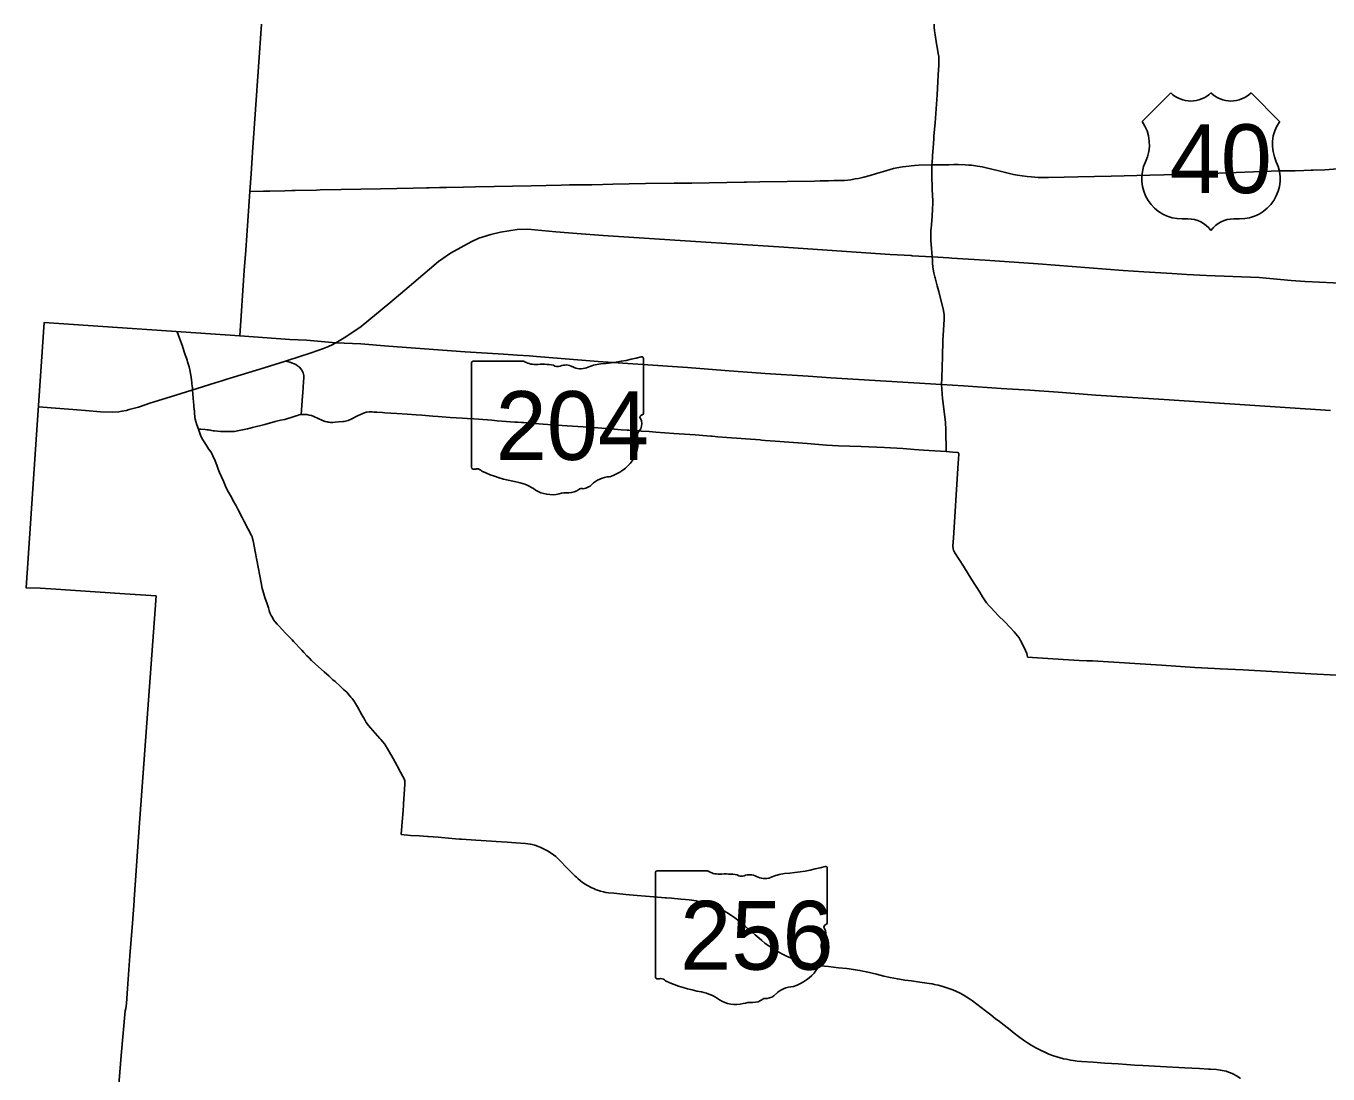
# Model space of a CAD drawing. Extents: x 1761803 to 2441803, y 509895 to 949895.
# Drawn here: x 1880621 to 1933337, y 771732 to 814167 of the extents above; entities that cross this region are included whole.
import ezdxf

# ---------------------------------------------------------------- set-up
doc = ezdxf.new("R2010")
doc.units = 0
for name, color, linetype in [('GM_X_County', 7, 'Continuous'), ('GM_X_County_Road_Text', 7, 'Continuous'), ('GM_X_Minor_Lake', 7, 'Continuous'), ('GM_X_Minor_River', 7, 'Continuous'), ('GM_X_Minor_River_Text', 7, 'Continuous'), ('GM_X_Township_Road', 7, 'Continuous')]:
    doc.layers.add(name, color=color, linetype=linetype)

msp = doc.modelspace()

# ---------------------------------------------------------------- linework, layer by layer
at = {"layer": 'GM_X_County'}
for points in [[(1890151, 814240), (1889790, 809054), (1889730, 808187), (1889680, 807466), (1889514, 805092), (1889457, 804269), (1889273, 801617), (1891303, 801473), (1891975, 801450), (1893167, 801341), (1894181, 801293), (1895291, 801208), (1898404, 800970), (1899948, 800886), (1900525, 800845), (1900989, 800810), (1901286, 800791), (1903789, 800582), (1907402, 800335), (1908911, 800219), (1910549, 800095), (1912289, 799987), (1913214, 799928), (1917684, 799645), (1918576, 799593), (1920103, 799495), (1921268, 799418), (1922415, 799341), (1923944, 799214), (1926704, 799049), (1933445, 798603)], [(1889273, 801617), (1881354, 802158), (1880996, 796827), (1880621, 791420), (1881199, 791408), (1881620, 791382), (1884619, 791174), (1885889, 791091), (1885509, 785950), (1885182, 781522), (1884997, 778795), (1885000, 778743), (1884928, 777838), (1884830, 776510), (1884735, 775195), (1884687, 774579), (1884665, 774383), (1884630, 774290), (1884479, 772480), (1884260, 769783)]]:
    msp.add_lwpolyline(points, dxfattribs=at)
at = {"layer": 'GM_X_County_Road_Text'}
for p, q in [((1926973, 811463), (1925812, 810303)), ((1931381, 810303), (1930221, 811463)), ((1927437, 806358), (1927669, 806358)), ((1929525, 806358), (1929757, 806358))]:
    msp.add_line(p, q, dxfattribs=at)
for centre, radius, start, end in [((1927785, 812291), 1160, 225.573, 314.427), ((1929409, 812291), 1160, 225.573, 314.427), ((1924482, 809371), 1624, 334.5471, 35.0009), ((1932712, 809371), 1624, 144.9991, 205.4529), ((1927418, 807982), 1624, 154.8319, 270.6383), ((1929775, 807982), 1624, 269.3617, 25.1681), ((1927669, 805198), 1160, 36.8699, 90), ((1929525, 805198), 1160, 90, 143.1301)]:
    msp.add_arc(centre, radius, start, end, dxfattribs=at)
at = {"layer": 'GM_X_Minor_Lake'}
for points in [[(1917501, 813385), (1917491, 813445), (1917428, 813817), (1917410, 813975), (1917397, 814123), (1917398, 814247)], [(1917384, 809726), (1917428, 810245), (1917510, 811384), (1917540, 811910), (1917553, 812190), (1917575, 812580), (1917584, 812745), (1917577, 812929), (1917560, 813054), (1917526, 813229), (1917501, 813385)], [(1917360, 809403), (1917375, 809622), (1917384, 809726)], [(1917321, 808864), (1917325, 808927), (1917360, 809403)], [(1917308, 808648), (1917321, 808864)], [(1917296, 808208), (1917294, 808313), (1917302, 808540)], [(1917316, 807481), (1917311, 807589), (1917308, 807780), (1917302, 807946), (1917296, 808208)], [(1917302, 808540), (1917308, 808648)], [(1917306, 806453), (1917307, 806463), (1917325, 806747), (1917333, 806993), (1917333, 807020), (1917320, 807386), (1917316, 807481)], [(1917260, 805846), (1917261, 805903), (1917265, 805967), (1917279, 806129)], [(1917279, 806129), (1917280, 806143), (1917306, 806453)], [(1917310, 804823), (1917310, 804823), (1917264, 805339), (1917256, 805481), (1917257, 805733), (1917260, 805846)], [(1917415, 804018), (1917373, 804171), (1917342, 804404), (1917325, 804572), (1917318, 804685), (1917310, 804823)], [(1917568, 803452), (1917513, 803648), (1917428, 803971), (1917415, 804018)], [(1917684, 799645), (1917698, 799926), (1917725, 800792), (1917745, 801424), (1917797, 802299), (1917797, 802469), (1917775, 802653), (1917577, 803419), (1917568, 803452)], [(1886742, 801790), (1886797, 801638), (1886957, 801199), (1886960, 801190)], [(1886742, 801790), (1886797, 801638), (1886957, 801199), (1886960, 801190)], [(1886960, 801190), (1887070, 800859), (1887119, 800716), (1887142, 800633)], [(1887142, 800633), (1887162, 800563), (1887224, 800365), (1887258, 800242), (1887285, 800095), (1887307, 799953), (1887318, 799830)], [(1891121, 800590), (1891298, 800552), (1891414, 800515), (1891539, 800466), (1891615, 800409), (1891689, 800354), (1891753, 800283), (1891793, 800229), (1891846, 800118), (1891864, 800015), (1891864, 799918), (1891856, 799758)], [(1887318, 799830), (1887328, 799727), (1887336, 799666)], [(1891856, 799758), (1891832, 799322), (1891820, 799176)], [(1887336, 799666), (1887344, 799605), (1887355, 799491), (1887359, 799421), (1887404, 798931), (1887416, 798829), (1887420, 798773), (1887440, 798543), (1887447, 798459), (1887453, 798369), (1887461, 798315), (1887472, 798247), (1887473, 798243)], [(1891820, 799176), (1891762, 798437)], [(1917882, 796932), (1917868, 797816), (1917846, 798109), (1917804, 798456), (1917729, 799085), (1917684, 799645)], [(1887473, 798243), (1887493, 798159), (1887536, 798018), (1887599, 797836)], [(1889589, 797852), (1889794, 797906), (1890292, 798037), (1890712, 798152), (1890930, 798208), (1891098, 798238), (1891473, 798351), (1891564, 798381)], [(1891564, 798381), (1891616, 798398), (1891683, 798421), (1891762, 798437)], [(1891762, 798437), (1891888, 798437), (1891985, 798432), (1892088, 798415), (1892178, 798394), (1892280, 798352), (1892624, 798191), (1892729, 798155), (1892814, 798133), (1892859, 798125), (1892900, 798121), (1892944, 798118), (1892992, 798118), (1893037, 798119), (1893143, 798127), (1893274, 798135), (1893450, 798151), (1893507, 798159), (1893557, 798168), (1893666, 798199), (1893784, 798250), (1894044, 798381), (1894163, 798440), (1894226, 798470), (1894280, 798491), (1894329, 798509), (1894395, 798525), (1894420, 798530), (1894517, 798538), (1894632, 798540), (1894709, 798536), (1894825, 798528)], [(1894825, 798528), (1895061, 798512), (1895148, 798506), (1895639, 798473), (1896057, 798446), (1896422, 798418), (1896652, 798403), (1897098, 798371), (1897305, 798356), (1897796, 798320), (1898281, 798291), (1898484, 798273), (1898748, 798255), (1899303, 798214), (1899477, 798201), (1899692, 798185), (1900063, 798158), (1900414, 798130), (1900529, 798123), (1900689, 798112)], [(1887599, 797836), (1887683, 797605), (1887727, 797506), (1887777, 797415), (1887827, 797336), (1887925, 797182), (1888013, 797049), (1888098, 796930), (1888157, 796825), (1888191, 796764), (1888237, 796648)], [(1887599, 797836), (1887692, 797836), (1887868, 797826), (1887950, 797820), (1888008, 797812), (1888074, 797799), (1888091, 797796)], [(1888091, 797796), (1888144, 797784), (1888200, 797775), (1888249, 797769), (1888497, 797751), (1888789, 797742), (1888802, 797742)], [(1888802, 797742), (1888967, 797743), (1889068, 797754), (1889251, 797789), (1889386, 797811), (1889589, 797852)], [(1900689, 798112), (1900757, 798108), (1900954, 798094), (1901199, 798076), (1902115, 798011), (1903596, 797909)], [(1903596, 797909), (1904452, 797836), (1904713, 797820), (1904959, 797807), (1905034, 797803), (1905302, 797787), (1905547, 797767), (1905858, 797745), (1906127, 797727), (1906856, 797673), (1907714, 797613)], [(1907714, 797613), (1908193, 797574), (1908346, 797561)], [(1908346, 797561), (1908399, 797556), (1908634, 797537), (1908994, 797508), (1910347, 797406), (1910399, 797402)], [(1910399, 797402), (1910555, 797390)], [(1910555, 797390), (1910958, 797359), (1912250, 797260), (1913034, 797198), (1913513, 797172), (1914434, 797137), (1915385, 797102), (1916119, 797054), (1916582, 797017), (1916959, 796997), (1917882, 796932)], [(1888237, 796648), (1888247, 796623), (1888340, 796380), (1888402, 796223), (1888461, 796085), (1888614, 795732), (1888698, 795531), (1888779, 795363), (1888853, 795230), (1888934, 795090), (1889001, 794974), (1889128, 794738), (1889210, 794582), (1889373, 794259), (1889452, 794099), (1889615, 793791), (1889690, 793646), (1889726, 793579), (1889750, 793532), (1889772, 793481), (1889794, 793416), (1889814, 793324), (1889871, 793042), (1889898, 792895), (1889968, 792533), (1890143, 791624), (1890186, 791397), (1890208, 791310), (1890236, 791213), (1890293, 791028), (1890382, 790774), (1890436, 790609), (1890466, 790504), (1890498, 790409), (1890518, 790352), (1890546, 790294), (1890567, 790256), (1890594, 790210), (1890643, 790128), (1890702, 790045), (1890785, 789948), (1890807, 789927)], [(1917882, 796932), (1918148, 796915), (1918344, 796901), (1918376, 796884), (1918381, 796876), (1918383, 796867), (1918384, 796848), (1918384, 796828), (1918346, 796263), (1918170, 793425), (1918153, 793114), (1918155, 792998), (1918177, 792939), (1918232, 792838), (1918582, 792290), (1918920, 791748), (1919239, 791239), (1919347, 791058), (1919514, 790811), (1919623, 790682), (1919698, 790602), (1919834, 790464), (1920003, 790289), (1920236, 790055), (1920481, 789802), (1920632, 789635), (1920771, 789468), (1920828, 789393), (1920890, 789288), (1920942, 789188), (1921086, 788878), (1921140, 788759), (1921161, 788697), (1921174, 788612)], [(1890807, 789927), (1890837, 789896), (1891142, 789571), (1891173, 789539)], [(1891173, 789539), (1891395, 789308)], [(1891395, 789308), (1891456, 789244), (1891791, 788887), (1891870, 788803)], [(1891870, 788803), (1891996, 788670), (1892086, 788577), (1892184, 788481), (1892466, 788224)], [(1892466, 788224), (1892697, 788014), (1892891, 787837), (1893047, 787696)], [(1921174, 788612), (1921784, 788573), (1922832, 788507), (1923267, 788480), (1923569, 788461), (1923801, 788461), (1926597, 788281), (1927949, 788195), (1928747, 788145), (1928972, 788135), (1929900, 788094), (1931066, 788028), (1932642, 787931), (1933679, 787882), (1933866, 787871), (1934236, 787845), (1934539, 787836), (1938763, 787625), (1939615, 787583)], [(1893047, 787696), (1893132, 787619), (1893344, 787430), (1893478, 787306), (1893604, 787189), (1893709, 787076), (1893777, 786996), (1893826, 786931), (1893915, 786796), (1894036, 786599), (1894218, 786275), (1894323, 786097), (1894398, 785968), (1894485, 785842), (1894565, 785743), (1894664, 785638), (1894757, 785533), (1894944, 785323), (1894990, 785272), (1895072, 785182), (1895136, 785102), (1895174, 785047)], [(1895174, 785047), (1895182, 785035), (1895246, 784931), (1895482, 784509), (1895648, 784205), (1895788, 783947), (1895881, 783778), (1895929, 783684), (1895946, 783638), (1895957, 783600), (1895964, 783555), (1895963, 783472), (1895947, 783260), (1895904, 782667), (1895900, 782619)], [(1895900, 782619), (1895885, 782406), (1895861, 782094), (1895838, 781768), (1895811, 781424)], [(1895811, 781424), (1896186, 781394), (1896551, 781369), (1896877, 781344)], [(1896877, 781344), (1896908, 781342), (1897304, 781317), (1897442, 781306), (1898013, 781253), (1898167, 781244)], [(1898167, 781244), (1898253, 781239), (1898834, 781201)], [(1898834, 781201), (1899470, 781160), (1899655, 781147), (1900103, 781119), (1900447, 781098), (1900844, 781068), (1900935, 781057), (1901036, 781039), (1901119, 781021), (1901221, 780995), (1901337, 780956), (1901469, 780904), (1901629, 780828), (1901741, 780763), (1901887, 780674), (1901979, 780606), (1902070, 780532), (1902240, 780374), (1902524, 780085), (1902861, 779743), (1902903, 779703), (1902960, 779650), (1903070, 779555), (1903144, 779499), (1903230, 779436), (1903360, 779360), (1903504, 779281), (1903660, 779212), (1903672, 779207)], [(1903672, 779207), (1903765, 779170), (1903886, 779133), (1904001, 779104), (1904097, 779086), (1904206, 779071), (1904421, 779047), (1904901, 779005), (1905367, 778964), (1906039, 778908), (1906495, 778867), (1906548, 778864)], [(1906548, 778864), (1906756, 778848), (1907132, 778813), (1907327, 778796), (1907470, 778786), (1907569, 778771), (1907754, 778739), (1907894, 778709), (1908045, 778669), (1908234, 778613), (1908468, 778526), (1908627, 778461), (1908786, 778382), (1908881, 778332), (1909000, 778264), (1909185, 778150), (1909323, 778051), (1909434, 777967), (1909546, 777880), (1909650, 777793), (1909746, 777709), (1909839, 777625), (1910022, 777469), (1910146, 777364), (1910306, 777229), (1910409, 777137), (1910536, 777035), (1910706, 776913), (1910818, 776836), (1910918, 776772), (1911103, 776663), (1911251, 776583), (1911386, 776519), (1911513, 776459), (1911676, 776394), (1911869, 776323), (1912026, 776272), (1912146, 776238), (1912291, 776202), (1912446, 776169), (1912610, 776138), (1912792, 776117), (1913108, 776081), (1913522, 776034), (1913859, 775997), (1914120, 775965), (1914197, 775955), (1914378, 775924), (1914501, 775897), (1914651, 775861), (1915056, 775769), (1915360, 775698), (1915614, 775639), (1915762, 775607), (1915905, 775579), (1915992, 775567), (1916203, 775534), (1916470, 775497), (1916805, 775450), (1917005, 775425), (1917187, 775398), (1917311, 775379), (1917412, 775359), (1917555, 775329), (1917700, 775292), (1917871, 775240), (1918025, 775186), (1918149, 775135), (1918293, 775075), (1918412, 775014), (1918566, 774934), (1918713, 774844), (1918824, 774774), (1918943, 774691), (1919124, 774554), (1919291, 774425), (1919469, 774285), (1919680, 774125), (1919862, 773984), (1920037, 773850), (1920221, 773705), (1920471, 773517), (1920634, 773390), (1920806, 773253), (1921013, 773098), (1921172, 772989), (1921319, 772897), (1921506, 772788), (1921696, 772690), (1921897, 772598), (1922031, 772540), (1922187, 772485), (1922358, 772427), (1922633, 772351), (1922744, 772333), (1922918, 772295), (1923021, 772273), (1923184, 772255), (1923354, 772239), (1923829, 772206), (1924306, 772171), (1924844, 772137), (1925181, 772114), (1925506, 772092), (1925842, 772078), (1926553, 772036), (1927541, 771981), (1927829, 771970), (1928142, 771949), (1928503, 771927), (1928580, 771922)], [(1928580, 771922), (1928822, 771907), (1928978, 771889), (1929138, 771858), (1929210, 771840), (1929303, 771809), (1929386, 771777), (1929489, 771739), (1929638, 771652), (1929779, 771559), (1929802, 771542)]]:
    msp.add_lwpolyline(points, dxfattribs=at)
at = {"layer": 'GM_X_Minor_River'}
for points in [[(1893167, 801341), (1893576, 801576), (1894194, 802002), (1895349, 802960), (1896136, 803624), (1896321, 803779), (1897320, 804631), (1897808, 804965), (1898638, 805432), (1898953, 805571), (1899444, 805721), (1899837, 805825), (1900506, 805928), (1900937, 805944), (1902079, 805829), (1902917, 805765), (1903996, 805690), (1907734, 805448)], [(1907734, 805448), (1911103, 805229)], [(1911103, 805229), (1915612, 804916), (1916457, 804870), (1916505, 804867), (1917310, 804823)], [(1917310, 804823), (1917987, 804779), (1918103, 804771), (1919455, 804681), (1921607, 804533)], [(1921607, 804533), (1925046, 804265), (1925888, 804213), (1927022, 804147), (1927626, 804112), (1928423, 804064), (1930547, 803979), (1931849, 803860), (1932411, 803824), (1932996, 803790), (1933552, 803763), (1936392, 803629), (1937214, 803614), (1937778, 803653), (1938064, 803686)], [(1891121, 800590), (1891708, 800782), (1892127, 800922), (1892436, 801025), (1892668, 801110), (1892874, 801187), (1893021, 801254), (1893167, 801341)], [(1888712, 799848), (1890258, 800330), (1891121, 800590)], [(1887769, 799557), (1888323, 799727), (1888512, 799785), (1888712, 799848)], [(1885675, 798907), (1885764, 798937), (1885815, 798952), (1886475, 799156), (1887769, 799557)], [(1881125, 798749), (1883032, 798601), (1883638, 798550), (1884118, 798535), (1884374, 798551), (1884502, 798571), (1884674, 798601)], [(1884674, 798601), (1884684, 798603), (1884800, 798633), (1885175, 798738), (1885675, 798907)]]:
    msp.add_lwpolyline(points, dxfattribs=at)
at = {"layer": 'GM_X_Minor_River_Text'}
for points in [[(1914326, 808000), (1914548, 808054), (1914797, 808120), (1915060, 808197), (1915430, 808308), (1915616, 808359), (1915751, 808392), (1915885, 808422), (1916108, 808462), (1916246, 808482), (1916360, 808497), (1916456, 808506), (1916593, 808519), (1916775, 808529), (1917302, 808540)], [(1917302, 808540), (1917989, 808553), (1918186, 808558), (1918363, 808559), (1918650, 808548), (1918798, 808538), (1918899, 808527), (1919149, 808495), (1919336, 808464), (1919437, 808442), (1920014, 808302), (1920328, 808222), (1920601, 808157), (1920762, 808126)], [(1921927, 808035), (1922024, 808039), (1922660, 808052), (1923208, 808064), (1924565, 808089), (1926129, 808124), (1927262, 808156), (1927848, 808169), (1931393, 808309), (1932006, 808305), (1932354, 808317), (1932659, 808328), (1932741, 808330), (1933216, 808345), (1934103, 808406), (1935088, 808430)], [(1893376, 807545), (1894977, 807574), (1896295, 807599), (1896836, 807614)], [(1896836, 807614), (1896941, 807616)], [(1896941, 807616), (1897360, 807628), (1897642, 807628), (1898328, 807643), (1898820, 807658), (1901070, 807698), (1902285, 807720), (1902629, 807734), (1903486, 807741), (1903524, 807742)], [(1903524, 807742), (1903972, 807757), (1904384, 807764)], [(1904384, 807764), (1905704, 807785), (1906866, 807798), (1907585, 807811), (1909692, 807844), (1909791, 807846), (1910338, 807858), (1911440, 807869)], [(1911440, 807869), (1911440, 807869), (1912552, 807892), (1912781, 807896)], [(1912781, 807896), (1912936, 807898)], [(1912936, 807898), (1913109, 807901), (1913325, 807911), (1913497, 807919), (1913761, 807910), (1914014, 807946), (1914190, 807975), (1914326, 808000)], [(1920762, 808126), (1920952, 808096), (1921161, 808070), (1921313, 808055), (1921469, 808041), (1921598, 808039), (1921714, 808035)], [(1921714, 808035), (1921821, 808031)], [(1921821, 808031), (1921927, 808035)], [(1889680, 807466), (1890242, 807479), (1890495, 807484)], [(1890495, 807484), (1891106, 807498)], [(1891106, 807498), (1891387, 807504), (1891513, 807507)], [(1891513, 807507), (1892379, 807527)], [(1892379, 807527), (1892537, 807530)], [(1892537, 807530), (1893376, 807545)]]:
    msp.add_lwpolyline(points, dxfattribs=at)
at = {"layer": 'GM_X_Township_Road'}
for p, q in [((1898657, 800525), (1898657, 796299)), ((1900764, 800598), (1898725, 800598)), ((1905618, 798492), (1905618, 800703)), ((1905617, 798492), (1905618, 798492)), ((1906103, 779884), (1906103, 775658)), ((1908210, 779957), (1906172, 779957)), ((1913064, 777851), (1913064, 780062)), ((1913063, 777851), (1913064, 777851))]:
    msp.add_line(p, q, dxfattribs=at)
for centre, major_axis, start_param, end_param in [((1903138, 806360), (7382, 0), 4.814394, 5.042369), ((1905540, 800712), (77.5, 0), 6.141152, 7.989035), ((1898737, 800534), (80.6, 0), 1.712693, 3.28349), ((1901249, 801088), (782, 0), 4.042523, 4.731795), ((1901509, 798225), (2808, 0), 1.404758, 1.657858), ((1902146, 800556), (226, 0), 3.836095, 5.185415), ((1902477, 800067), (469, 0), 0.950623, 2.079405), ((1903083, 800738), (564, 0), 4.081561, 5.145723), ((1904080, 799307), (1485, 0), 1.699011, 2.107814), ((1905600, 798329), (120, 0), 1.883978, 3.671073), ((1904837, 798050), (720, 0), 5.934695, 6.695948), ((1905535, 798483), (82.9, 0), 5.05454, 6.418171), ((1905895, 797566), (524, 0), 2.387724, 3.262537), ((1903552, 797285), (1846, 0), 5.101752, 6.440018), ((1898737, 796289), (81.4, 0), 3.00124, 4.508301), ((1898750, 796722), (621, 0), 4.665946, 4.897461), ((1898877, 796055), (224, 0), 0.519207, 1.627899), ((1901703, 799852), (5331, 0), 4.195997, 4.488961), ((1900114, 794400), (1668, 0), 0.823519, 1.323587), ((1903049, 795889), (597, 0), 4.937069, 5.64225), ((1904330, 795112), (1011, 0), 1.647645, 2.488434), ((1901918, 796034), (1058, 0), 4.026481, 4.996735), ((1902529, 794572), (870, 0), 1.495662, 1.94098), ((1902607, 795717), (564, 0), 4.691044, 5.507374), ((1903117, 795308), (159, 0), 1.147584, 2.315152), ((1906183, 779893), (80.6, 0), 1.712693, 3.28349), ((1908696, 780448), (782, 0), 4.042523, 4.731795), ((1908955, 777584), (2808, 0), 1.404758, 1.657858), ((1909593, 779915), (226, 0), 3.836095, 5.185415), ((1909924, 779427), (469, 0), 0.950623, 2.079405), ((1910529, 780097), (564, 0), 4.081561, 5.145723), ((1911526, 778666), (1485, 0), 1.699011, 2.107814), ((1910585, 785719), (7382, 0), 4.814394, 5.042369), ((1912987, 780071), (77.5, 0), 6.141152, 7.989035), ((1913046, 777689), (120, 0), 1.883978, 3.671073), ((1912283, 777409), (720, 0), 5.934695, 6.695948), ((1912981, 777842), (82.9, 0), 5.05454, 6.418171), ((1913342, 776926), (524, 0), 2.387724, 3.262537), ((1910998, 776644), (1846, 0), 5.101752, 6.440018), ((1906184, 775649), (81.4, 0), 3.00124, 4.508301), ((1906196, 776081), (621, 0), 4.665946, 4.897461), ((1906323, 775414), (224, 0), 0.519207, 1.627899), ((1909150, 779211), (5331, 0), 4.195997, 4.488961), ((1907560, 773759), (1668, 0), 0.823519, 1.323587), ((1910495, 775248), (597, 0), 4.937069, 5.64225), ((1911777, 774471), (1011, 0), 1.647645, 2.488434), ((1909364, 775393), (1058, 0), 4.026481, 4.996735), ((1909976, 773932), (870, 0), 1.495662, 1.94098), ((1910053, 775077), (564, 0), 4.691044, 5.507374), ((1910563, 774667), (159, 0), 1.147584, 2.315152)]:
    msp.add_ellipse(centre, major_axis=major_axis, ratio=0.8, start_param=start_param, end_param=end_param, dxfattribs=at)

# ---------------------------------------------------------------- texts
at = {"layer": 'GM_X_County_Road_Text'}
msp.add_text('40', height=2784.4, dxfattribs=at).set_placement((1926924, 807402))
at = {"layer": 'GM_X_Township_Road'}
for s, p in [('204', (1899636, 796597)), ('256', (1907107, 775956))]:
    msp.add_text(s, height=2784.4, dxfattribs=at).set_placement(p)

doc.saveas('drawing.dxf')
